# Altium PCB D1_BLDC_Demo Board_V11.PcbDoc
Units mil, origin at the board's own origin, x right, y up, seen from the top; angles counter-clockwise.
Board outline 2680 x 1610 mil, 2 copper layers (TopLayer, BottomLayer); 61 components, 42 nets, 192 pads, 108 vias.
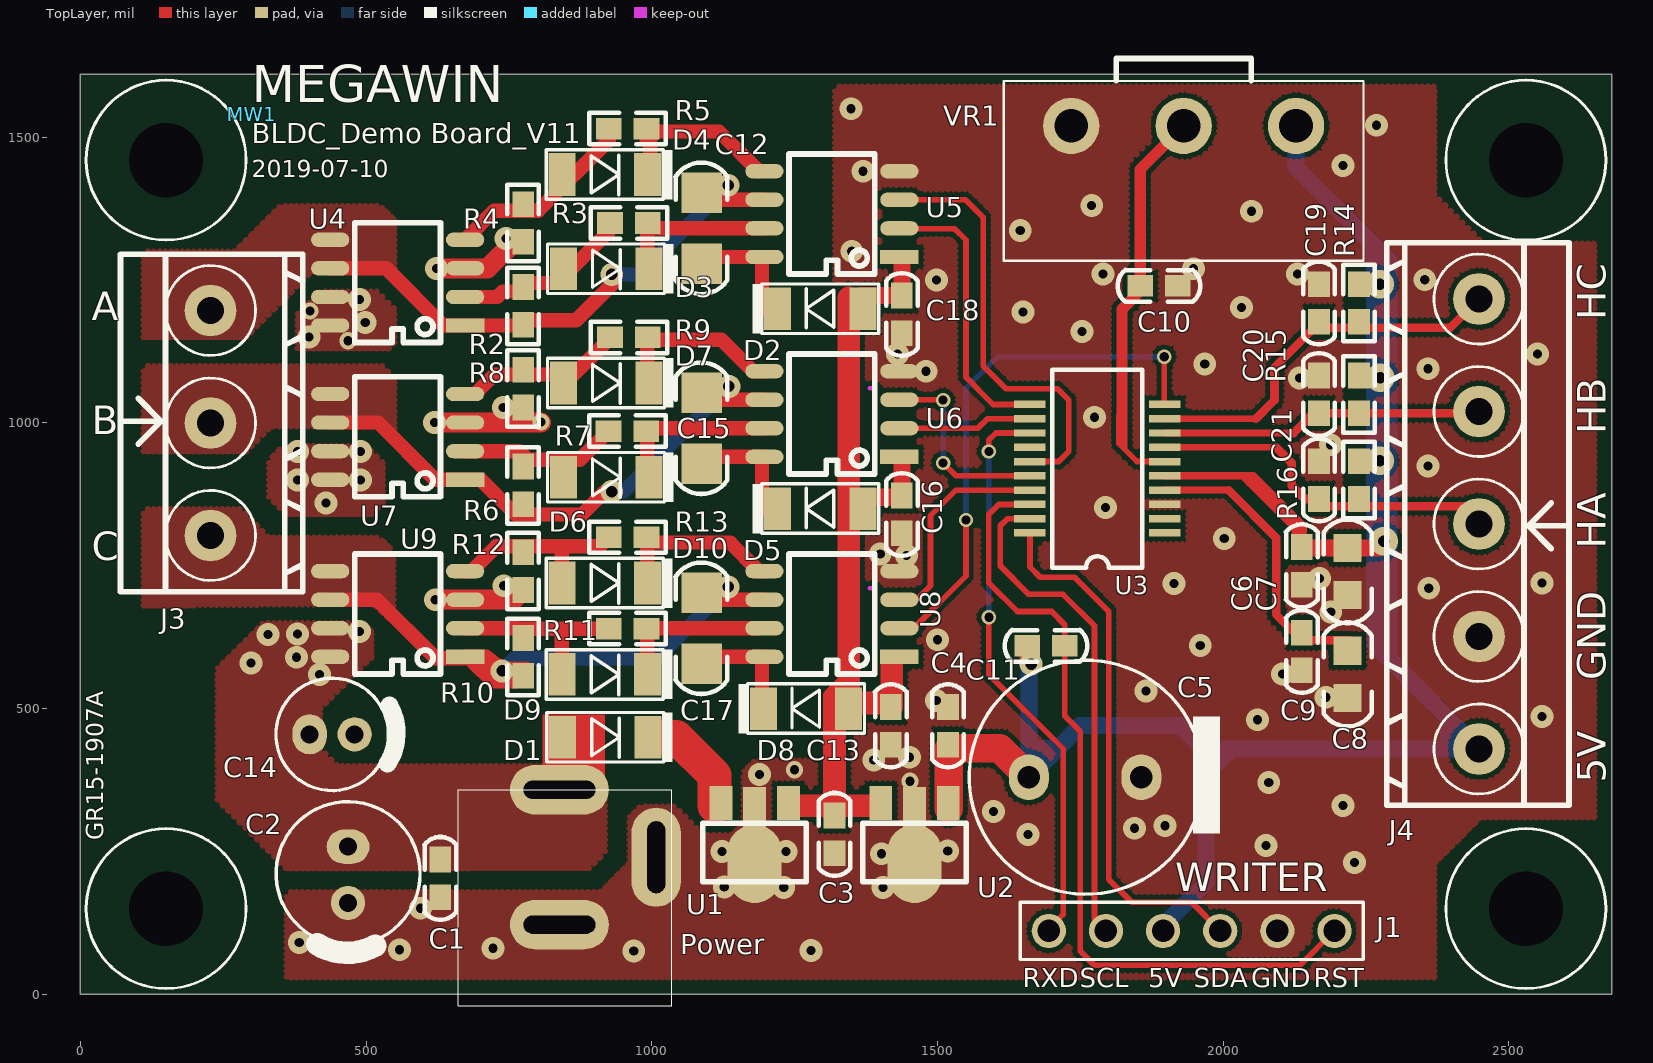
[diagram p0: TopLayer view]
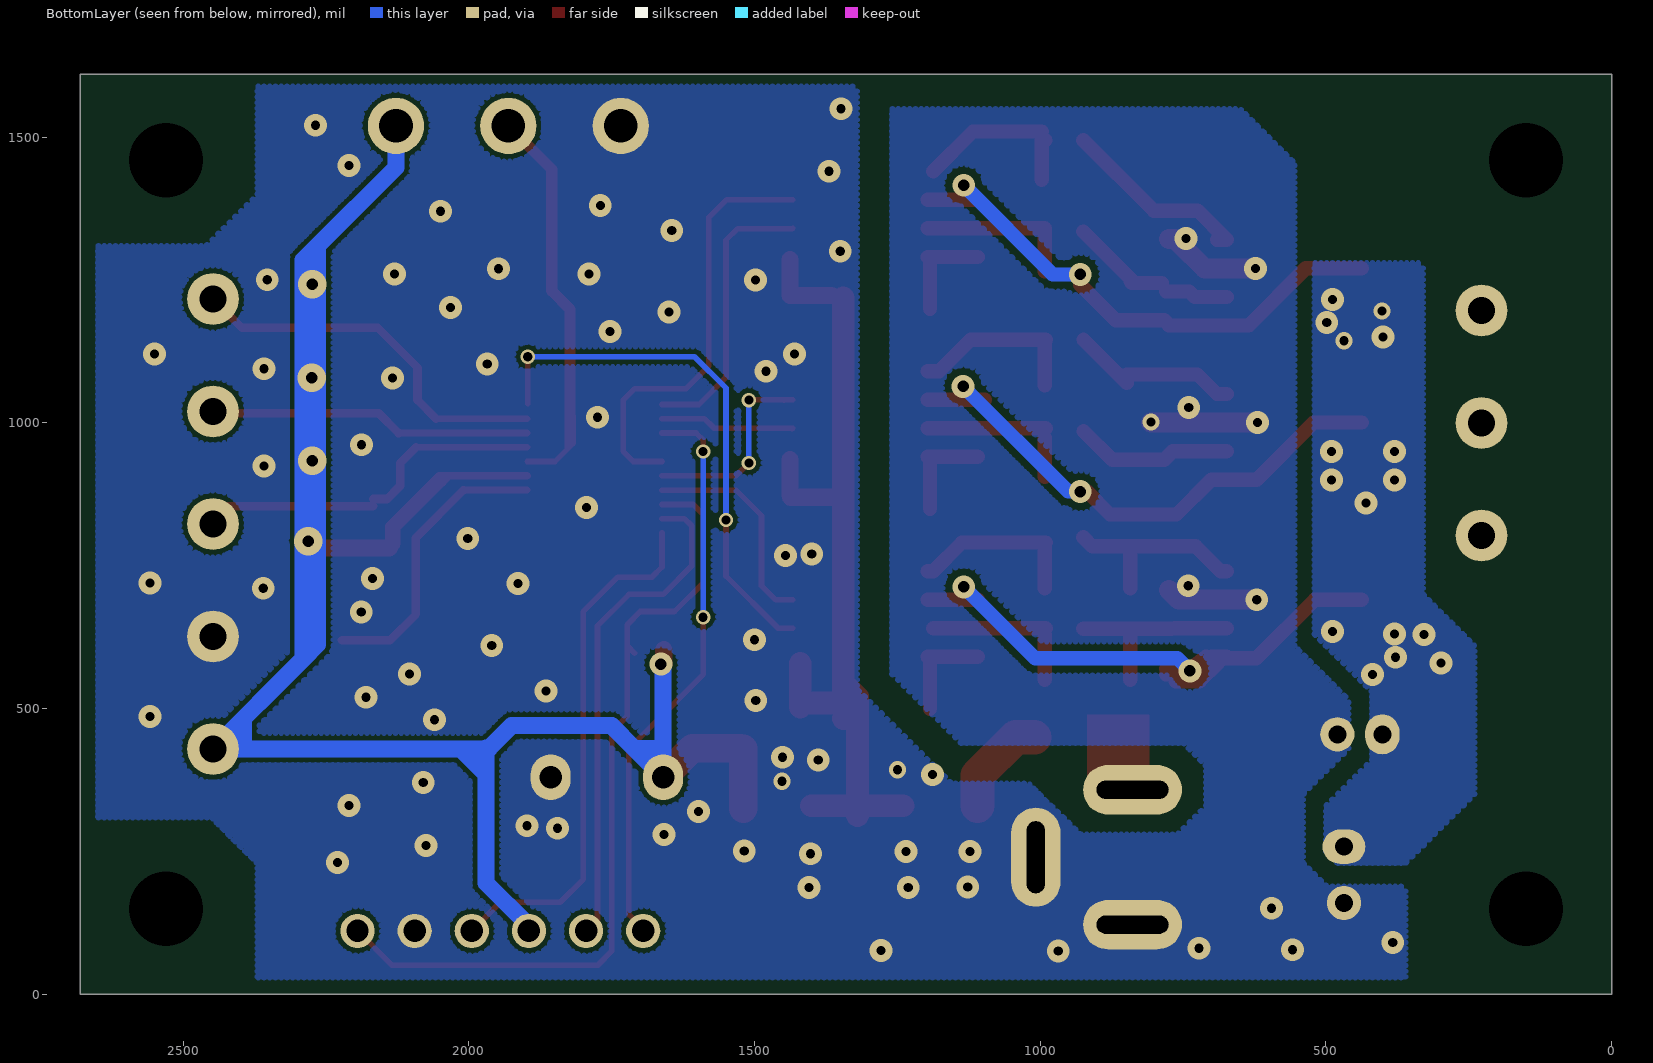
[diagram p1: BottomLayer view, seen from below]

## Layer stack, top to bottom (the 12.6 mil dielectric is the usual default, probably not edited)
TopLayer: signal copper 1.4
Dielectric: dielectric 12.6, FR-4, Dk 4.8
BottomLayer: signal copper 1.4

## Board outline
0,0 0,1610 2680,1610 2680,0

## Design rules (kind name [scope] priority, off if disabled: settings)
Clearance 12 [All] p1 off: gap=12
Clearance 10 [All] p2 off: gap=10
Clearance 8 [All] p3: gap=8
FabricationTestPointUsage TestPointUsage [All] p1: valid=0 allowmultiple=FALSE
FabricationTestpoint Testpoint [All] p1: side=3 testpointundercomponent=TRUE minsize=40 maxsize=100 preferedsize=60 minholesize=20 maxholesize=40 preferedholesize=32 testpointgrid=1 allowsidetop=TRUE allowsidebottom=TRUE usegrid=TRUE gridtolerance=0.01
HoleSize [All] p1: absolutevalues=TRUE maxlimit=500 minlimit=1 maxpercent=80.000 minpercent=20.000
PolygonConnect VIA [isvia] p1: connectstyle=Direct reliefconductorwidth=10 reliefentries=4 polygonreliefangle="90 Angle"
PolygonConnect PolygonConnect_1 [All] p2: connectstyle=Direct reliefconductorwidth=10 reliefentries=4 polygonreliefangle="90 Angle"
RoutingPriority [All] p1: routingpriority=4
RoutingVias [All] p1: holewidth=16 width=25 viastyle="Through Hole" minholewidth=16 minwidth=24 maxholewidth=28 maxwidth=50
SilkscreenOverComponentPads [All] p1: minsilkscreentomaskgap=10
SolderMaskExpansion [All] p1: expansion=4
Width [All] p1: maxlimit=100 minlimit=8 preferedwidth=10
23 further rules are at their usual default settings.

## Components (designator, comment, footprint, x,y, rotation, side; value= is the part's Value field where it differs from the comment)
C1 "0.1uF" 0603C 630,203 r90 top
C2 "35uF/35V" CEC060p025 468.46,258.43 r270 top
C3 "0.1uF" 0603C 1320,280 r90 top
C4 "0.1uF" 0603C 1518.46,470 r270 top
C5 "220uF_35V" CEC100p050 1758.42,380 r0 top
C6 "10uF" 0805C 2217.8,740 r270 top
C7 "0.1uF" 0603C 2137.8,750 r90 top
C8 "4.7uF" 0805C 2217.8,560 r270 top
C9 "0.1uF" 0603C 2137.8,600 r90 top
C10 "0.1uF" 0603C 1887.8,1240 r180 top
C11 "1uF" 0603C 1690,610 r180 top
C12 "10uF/1206" 1206C 1087.17,1340.67 r90 top
C13 "0.1uF" 0603C 1418.46,470 r90 top
C14 "10uF/50V" CEC5X11P2 440.63,455 r0 top
C15 "10uF/1206" 1206C 1087.17,990.67 r90 top
C16 "0.1uF" 0603C 1437.8,840 r90 top
C17 "10uF/1206" 1206C 1087.17,640.67 r90 top
C18 "0.1uF" 0603C 1437.8,1190 r90 top
C19 "0.1uF" 0603C 2167.8,1210 r270 top
C20 "0.1uF" 0603C 2167.8,1050 r270 top
C21 "0.1uF" 0603C 2167.8,900 r270 top
D1 "1N4148" D4148_SMD 918.46,450 r0 top
D2 "1N4148" D4148_SMD 1295,1200 r180 top
D3 "1N4148" D4148_SMD 920,1270 r0 top
D4 "1N4148" D4148_SMD 917.8,1435 r0 top
D5 "1N4148" D4148_SMD 1295,850 r180 top
D6 "1N4148" D4148_SMD 920,905 r0 top
D7 "1N4148" D4148_SMD 920,1070 r0 top
D8 "1N4148" D4148_SMD 1270,500 r180 top
D9 "1N4148" D4148_SMD 917.8,560 r0 top
D10 "1N4148" D4148_SMD 917.8,720 r0 top
J1 "CON6" PS6P254 1695,111 r0 top
J3 "Debug" PIN3_500_DT 227.8,1196.85 r270 top
J4 "CON5" PIN5_500_DT 2447.8,429.45 r90 top
MW1 "MEGAWIN" MEGAWIN_T 300,1540 r0 top
Power "DC JACK" JACK_DC 838.5,121.89 r90 top (schematic designator "Power 1")
R2 "30K" 0603R 775,1205 r270 top
R3 "33" 0603R 960,1350 r0 top
R4 "30K" 0603R 775,1350 r270 top
R5 "33" 0603R 957.8,1515 r0 top
R6 "30K" 0603R 775,890.67 r270 top
R7 "33" 0603R 957.17,985.67 r0 top
R8 "30K" 0603R 775,1060 r270 top
R9 "33" 0603R 960,1150 r0 top
R10 "30K" 0603R 775,590.67 r270 top
R11 "33" 0603R 957.8,640 r0 top
R12 "30K" 0603R 775,740.67 r270 top
R13 "33" 0603R 957.8,800 r0 top
R14 "1K" 0603R 2237.8,1210 r90 top
R15 "1K" 0603R 2237.8,1050 r90 top
R16 "1K" 0603R 2237.8,900 r90 top
U1 "UA78L15ACPK" SOT89 1180,335 r180 top
U2 "AIC1734A_50PXT / SOT89-3" SOT89 1460,335 r180 top
U3 "MG82F6D17_SSOP-20(150mil)" SSOP20_150P0635 1780,920 r90 top (schematic designator U6)
U4 "Si4946BEY" SO8_150P127 673.39,1170.67 r180 top
U5 "IR2101S" SO8_150P127 1433.39,1290.67 r180 top
U6 "IR2101S" SO8_150P127 1433.39,940.67 r180 top
U7 "Si4946BEY" SO8_150P127 673.39,900.67 r180 top
U8 "IR2101S" SO8_150P127 1433.39,590.67 r180 top
U9 "Si4946BEY" SO8_150P127 673.39,590.67 r180 top
VR1 "VR3-1" VR9_90 1930.94,1520 r270 top

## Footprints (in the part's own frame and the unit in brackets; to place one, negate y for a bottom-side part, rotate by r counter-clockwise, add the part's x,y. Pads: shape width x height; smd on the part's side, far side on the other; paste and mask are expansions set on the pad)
0603C [mil]
  rect 45x38 smd: 1(33,0) 2(-33,0)
  silkscreen extent -72,-28 72,28
0603R [mil]
  rect 45x38 smd: 1(33,0) 2(-33,0)
  silkscreen extent -67,-28 67,28
0805C [mm]
  rect 1.25x1.25 smd: 1(-1.05,0) 2(1.05,0)
  silkscreen extent -2.31,-1.07 2.31,1.07
1206C [mm]
  rect 1.8x1.8 smd: 1(-1.576,0) 2(1.576,0)
  silkscreen extent -2.92,-1.15 2.92,1.16
CEC5X11P2 [mil]
  oval 60x70 hole 31.5: 1(-39.37,0)
  round 60 hole 31.5: 2(39.37,0)
  silkscreen extent -98,-98 113,98
CEC060p025 [mil]
  oval 60x75 hole 31.5: 1(0,0)
  round 60 hole 31.5: 2(98.43,0)
  silkscreen extent -79,-126 186,126
CEC100p050 [mil]
  oval 70x80 hole 39.37: 1(-98.42,0) 2(98.42,0)
  silkscreen extent -203,-205 236,205
D4148_SMD [mm]
  rect 1.2x1.9 smd: 1(-1.9,0) 2(1.9,0)
  silkscreen extent -2.6,-1.1 3,1.1
JACK_DC [mm]
  oval 2.2x4.4 hole 0.8 slot 3.2 at 90 deg: 1(0,0) 3(6,0)
  oval 4.4x2.2 hole 0.8 slot 3.2 at 0 deg: 2(3,-4.3)
  silkscreen extent -3.6,-5 6,4.5
MEGAWIN_T [mil]
PIN3_500_DT [mm]
  round 2.3 hole 1.2: 1(0,0) 2(5,0) 3(10,0)
  silkscreen extent -2.5,-4 12.5,4.1
PIN5_500_DT [mm]
  round 2.3 hole 1.2: 1(0,0) 2(5,0) 3(10,0) 4(15,0) 5(20,0)
  silkscreen extent -2.5,-4 22.5,4.1
PS6P254 [mil]
  round 60 hole 39.37: 1(0,0) 2(100,0) 3(200,0) 4(300,0) 5(400,0) 6(500,0)
  silkscreen extent -50,-50 550,50
SO8_150P127 [mil]
  rect 67x25 smd: 1(0,0)
  oval 67x25 smd: 2(0,-50) 3(0,-100) 4(0,-150) 5(236.22,-150) 6(236.22,-100) 7(236.22,-50) 8(236.22,0)
  silkscreen extent 43,-180 193,30
SOT89 [mm]
  rect 1.016x1.5 smd: 1(-1.5,0) 3(1.5,0)
  oval 2.4x3.5 smd: 2(0,2.7)
  rect 1.016x2.6 smd: 2(0,0.6)
  silkscreen extent -2.3,0.9 2.3,3.5
SSOP20_150P0635 [mil]
  rect 13x55.12 smd: 1(-112.5,-118.11) 2(-87.5,-118.11) 3(-62.5,-118.11) 4(-37.5,-118.11) 5(-12.5,-118.11) 7(37.5,-118.11) 8(62.5,-118.11) 9(87.5,-118.11) 10(112.5,-118.11) 11(112.5,118.11) 12(87.5,118.11) 13(62.5,118.11) 14(37.5,118.11) 15(12.5,118.11) 16(-12.5,118.11) 17(-37.5,118.11) 18(-62.5,118.11) 19(-87.5,118.11) 20(-112.5,118.11)
  rect 13x55.12 smd mask+4: 6(12.5,-118.11)
  silkscreen extent -173,-79 173,79
VR9_90 [mm]
  round 2.5 hole 1.5: 1(0,5) 2(0,0) 3(0,-5)
  silkscreen extent -3,-8 6,8

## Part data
C1 C3 C4 C8 C9: library part "CAP NP_Dup1"
C2 C5: library part CAP_Dup1
C6 C7 C10 C11 C13 C16 C18 C19 C20 C21: library part "CAP NP"
C12 C14 C15 C17: library part CAP
D1 D2 D5 D8: library part ES1A/SM
J3: library part CON3
R2 R4 R6 R8 R10 R12: library part R
R3 R5 R7 R9 R11 R13 R14 R15 R16: library part RESISTOR
U2: library part AIC1734A_50PXT
U3: library part MG82G6D17_SSOP-20

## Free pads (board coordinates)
  round 100 hole 130 unplated: 1(150,150) 1(150,1460) 1(2530,150) 1(2530,1460)

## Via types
v1: diameter 40, hole 16, TopLayer to BottomLayer, tented both sides, 86 vias
v2: diameter 40, hole 20, TopLayer to BottomLayer, tented both sides, 7 vias
v3: diameter 25, hole 16, TopLayer to BottomLayer, 6 vias
v4: diameter 30, hole 16, TopLayer to BottomLayer, tented both sides, 5 vias
v5: diameter 50, hole 20, TopLayer to BottomLayer, tented both sides, 4 vias

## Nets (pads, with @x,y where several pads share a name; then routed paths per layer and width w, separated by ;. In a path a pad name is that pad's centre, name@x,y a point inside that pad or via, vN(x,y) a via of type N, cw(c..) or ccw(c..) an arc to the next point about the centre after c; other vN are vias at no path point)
15V: C3.1 C13.1 C16.1 C18.1 D2.1 D5.1 D8.1 U1.1 U2.3 U5.1 U6.1 U8.1 | length 1578.4
  TopLayer w25: 1312.37,522.37 1344.8,554.8
  TopLayer w30: D5.1@1364.8,870 C16.1@1437,870 ; D2.1@1365.6,1223 C18.1 U5.1@1437.8,1286.26 ; C16.1 U6.1@1437.8,936.26
  TopLayer w40: U1.1@1240,330 C3.1@1320,330 ; C3.1 C3.1@1320,330 ; 1320,520 1320,483 ; D8.1@1344.8,483 1320,483 ; D8.1 D8.1@1344.8,510 ; 1344.8,1219.2 1344.8,554.8 D8.1@1344.8,510 ; U2.3@1400.94,330 C3.1@1320,330 ; C13.1@1418.46,510 D8.1@1344.8,510 ; C13.1@1420,503 U8.1@1420,579 ; C3.1@1320,330 1320,483
"A DET": C21.1 J4.3 R16.2 U3.7 | length 635.8
  TopLayer w12: U3.7 2092.5,957.5
  TopLayer w15: 2092.5,957.5 2120,930 2120,890 2143,867 C21.1 ; C21.1@2167.8,854.21 2266,854.21 ; 2282.01,854.21 2266,854.21 ; J4.3@2457,854.21 2266,854.21
AB: U3.15 U5.3 | length 759.5
  TopLayer w10: U5.3 1549.33,1390.67 1580,1360 1580,1100 1620,1060 1710,1060 1730,1040 1730,950 1712.5,932.5 U3.15
AT: U3.11 U5.2 | length 496.7
  TopLayer w10: U5.2 1434.06,1340 1530,1340 1550,1320 1550,1080 1597.5,1032.5 U3.11
"B DET": C20.1 J4.4 R15.2 U3.8 | length 561
  TopLayer w12: U3.8 2123.3,982.5
  TopLayer w15: 2123.3,982.5 2157.8,1017 C20.1 R15.2 J4.4@2444.8,1017
BB: U3.16 U6.3 | length 362.5
  TopLayer w10: U6.3@1448.46,1040 1447.8,1040.67 U6.3 v3@1509.33,1040.67 ; v3(1510,930) 1532.5,907.5 U3.16
  BottomLayer w10: v3(1510,930) v3(1510,1040)
BT: U3.12 U6.2 | length 236.4
  TopLayer w10: U6.2@1434.06,990 U6.2 1570.67,990.67 1587.5,1007.5 U3.12
"C DET": C19.1 J4.5 R14.2 U3.9 | length 669.8
  TopLayer w12: U3.9 2057.5,1007.5
  TopLayer w15: 2057.5,1007.5 2090,1040 2090,1097 2160,1167 2167.8,1167 2397.94,1167 J4.5
CB: U3.17 U8.3 | length 379.9
  TopLayer w10: U8.3 1463.46,690.67 1487.8,715 1487.8,837.8 1532.5,882.5 U3.17
CT: U3.10 U8.2 | length 935.5
  TopLayer w10: U8.2 1458.46,640.67 1550,732.2 v3(1550,830) ; U3.10@1897,1033.61 v3(1897,1116)
  BottomLayer w10: v3(1550,830) 1550,1061 1605,1116 v3(1897,1116)
DC+: C1.1 C2.1 C14.1 D1.1 Power.3 U4.7 U4.8 U7.7 U7.8 U9.7 U9.8
  other v1: 418.46,560 298.46,580 378.46,590 328.46,630 380,630.63 488.46,635 430,860 380,900 490,900 380,950 490,950 400,1150.63 498.46,1176 488.46,1216
  other v4: 468.46,1144 402,1196
GND: C1.2 C2.2 C3.2 C4.2 C5.2 C6.2 C7.2 C8.2 C9.2 C10.2 C13.2 C14.2 C16.2 C18.2 C19.2 C20.2 C21.2 J1.5 J4.2 Power.1 Power.2 R4.1 R8.1 R12.1 U1.2 U2.2 U3.3 U4.3 U5.4 U6.4 U7.3 U8.4 U9.3 VR1.3 | length 522.8
  TopLayer w35: v1@618.46,1000.67 v1(620,1000.63) U7.3 740,1000.67 775,1000.67 v4@806,1000.67 ; v1@620,690.67 v1(621,690.63) U9.3 741,690.67 758,690.67 761.67,694.33 R12.1 ; v1(623,1270.67) U4.3 712.67,1270.67 755,1313 764,1322 R4.1@775,1322
  other v1: 968.46,76 1278.46,77 558.46,78 722,80.63 383,90.63 595,150.63 1231,187 1405,187 1127,188 2230,230.63 1402,246 1123,250 1235,250 1518,251 2075,260.63 1658.46,280 1845,290.63 1898.46,295 1598.46,320 2210,330.63 2080,370.63 1188.46,385 1388.46,410 1451,415 2060,480.63 2558.46,486 1498,514 2180,520 1865,530.63 2104,560.63 1960,610.63 1500,620.63 2188.46,669 2360,710.63 741,715 1914,719 2558.46,720 2168.46,728 1446,768 1400,770.63 2002,798 1794,852 2358.46,925 2188,962 1775,1010 740,1027 2134,1079 1480,1090.63 2358.46,1095 1968,1103 1430,1120.63 2550,1120.63 1753,1160 1650,1194 2032,1202 1498.46,1250 2353,1250.63 1790,1260.63 2130,1260.63 1948.46,1270 1350,1300.63 745,1323 1645,1337 2050,1370.63 1770,1380.63 1370,1440.63 2210,1450.63 2268.46,1521 1348.46,1550
  other v4: 1452,373 1250,393 806,1002
NetC12_1: C12.1 D2.2 U5.8 | length 174.4
  TopLayer w25: C12.1@1109.22,1290.67 U5.8 ; 1192.99,1200 U5.8@1192.99,1286.5
NetC15_1: C15.1 D5.2 U6.8 | length 174.4
  TopLayer w25: C15.1@1109.22,940.67 U6.8 ; 1192.99,850 U6.8@1192.99,936.5
NetC17_1: C17.1 D8.2 U8.8 | length 174.4
  TopLayer w25: C17.1@1109.22,590.67 U8.8 ; D8.2@1192.99,500 U8.8@1192.99,586.5
NetD1_2: D1.2 U1.3 | length 180.7
  TopLayer w60: D1.2@1010,450 1042.99,450 1110,382.99 1110,335 U1.3@1110,330
NetD3_1: D3.1 R2.2 R3.2 U4.2 | length 293.1
  TopLayer w25: U4.2 729.67,1220.67 739,1230 R2.2@780,1230 ; R2.2@787.2,1245 D3.1@834.8,1245 ; D3.1@840,1245 D3.1@834.8,1245 ; D3.1@842.99,1250.67 D3.1@840.46,1250.67 ; R3.2@924.8,1335 D3.1@840.46,1250.67 ; D3.1@834.8,1245 D3.1@840.46,1250.67
NetD3_2: D3.2 R3.1 U5.7 | length 274.5
  TopLayer w25: D3.2@991.97,1265.67 R3.1@991.97,1335 ; R3.1@991.97,1340.67 U5.7
NetD4_1: D4.1 R4.2 R5.2 U4.4 | length 340.9
  TopLayer w25: U4.4@690.67,1320.67 U4.4 724.41,1371.69 801.49,1371.69 924.8,1495
NetD4_2: D4.2 R5.1 U5.5 | length 298.1
  TopLayer w25: 990.8,1495 997.17,1495 ; D4.2@997.17,1425.67 997.17,1495 ; R5.1@997.17,1498.67 997.17,1495 ; R5.1@997.17,1510 1117.83,1510 U5.5@1187.17,1440.67
NetD6_1: D6.1 R6.2 R7.2 U7.2 | length 277.7
  TopLayer w25: U7.2 768,950.67 783,935.67 874.17,935.67 R7.2
NetD6_2: D6.2 R7.1 U6.7 | length 275.2
  TopLayer w25: R7.1@990.17,990.67 U6.7 ; D6.2@991.97,905.67 R7.1@991.97,973.87
NetD7_1: D7.1 R8.2 R9.2 U7.4 | length 296.3
  TopLayer w25: U7.4 690.67,1050.67 725,1085 D7.1@848.5,1085 ; D7.1@848.5,1070 R9.2@924.17,1145.67
NetD7_2: D7.2 R9.1 U6.5 | length 308
  TopLayer w25: R9.1@990.17,1145.67 1122.17,1145.67 1177.17,1090.67 U6.5 ; D7.2@991.97,1065.67 R9.1@991.97,1143.87
NetD9_1: D9.1 R10.2 R11.2 U9.2 | length 334.1
  TopLayer w25: U9.2 R10.2@764.17,640.67 ; R10.2@770.83,640 775,640 842.36,640 ; D9.1@842.36,550.67 842.36,560 842.36,640 ; R11.2 842.36,640
NetD9_2: D9.2 R11.1 U8.7 | length 275.2
  TopLayer w25: R11.1@990.17,640.67 990.8,640.67 U8.7@1187.17,640.67 ; D9.2@991.97,550.67 991.97,560 R11.1@991.97,628.87
NetD10_1: D10.1 R12.2 R13.2 U9.4 | length 346
  TopLayer w25: U9.4 684.46,740.67 727.8,784 908.8,784 R13.2 ; D10.1@842.36,710.67 842.36,780.67
NetD10_2: D10.2 R13.1 U8.5 | length 305.9
  TopLayer w25: R13.1@990.17,790.67 1137.17,790.67 1187.17,740.67 U8.5 ; D10.2@991.97,710.67 R13.1@991.97,788.87
NetJ2_1: 
NetJ2_2: 
NetJ2_3: 
OCD_SCL: J1.2 U3.19 | length 877.8
  TopLayer w10: U3.19 1622.5,832.5 1610,820 1610,750 1660,700 1720,700 1775,645 1775,131 J1.2
OCD_SDA: J1.4 U3.20 | length 931.1
  TopLayer w10: U3.20 1661.89,748.11 1680,730 1740,730 1800,670 1800,201 1840,161 1945,161 J1.4
RST: C11.2 J1.6 U3.18 | length 1443.6
  TopLayer w10: U3.18 1607.5,857.5 1590,840 1590,720 1640,670 1700,670 1723,647 1723,487 1750,460 1750,75.63 1774.63,51 2134.37,51 J1.6@2195,111.63 ; C11.2@1710,597 C11.2
RXD0: J1.1 U3.13 | length 1000.9
  TopLayer w10: v3(1590,660) 1590,560 1720,430 1720,139.63 J1.1@1692,111.63 ; v3(1590,950) 1590,970 1602.5,982.5 U3.13
  BottomLayer w10: v3(1590,660) v3(1590,950)
RXD1: 
U: C12.2 J3.1 R2.1 U4.1 U4.5 U4.6 U5.6 | length 966.4
  TopLayer w25: U4.6 535.13,1270.67 635.13,1170.67 U4.1 ; U4.1@702,1170.67 U4.1 ; R2.1@775,1170.67 U4.1 ; R2.1 783,1180 868,1180 930,1242 v2(930,1260) ; C12.2@1109.22,1390.67 U5.6
  BottomLayer w25: v2(930,1260) 978,1260 v2(1134,1416)
V: C15.2 J3.2 R6.1 U6.6 U7.1 U7.5 U7.6 | length 945
  TopLayer w25: U7.6 521.13,1000.67 621.13,900.67 U7.1 700.8,900.67 761.46,840 877.8,840 v2@917.8,880 ; C15.2@1097.17,1040.67 U6.6
  BottomLayer w25: v2(930,880) 951,880 v2(1135,1064)
VDD5V: C4.1 C5.1 C6.1 C7.1 C11.1 J1.3 J4.1 R14.1 R15.1 R16.1 U2.1 U3.5 VR1.1 | length 4404.5
  TopLayer w13: U3.5 2052.5,907.5 2140,820 C7.1@2140,790
  TopLayer w15: 2036.38,906.62 2058.4,884.6 ; C7.1@2132,788.8 C7.1 C7.1@2139.46,781.34
  TopLayer w25: 2050,900 2132,818 C7.1@2132,788.8
  TopLayer w30: v2@1659,578 C11.1@1659,603 ; C7.1@2139.46,781.34 C6.1 v5@2272.04,781.34
  TopLayer w50: U2.1@1520,325 1520,335 C4.1@1520,430 ; C4.1@1525,430.63 1609.37,430.63 C5.1
  BottomLayer w30: v2@1660,578 C5.1 1710.02,430.02 ; 1661.55,429.91 1710.02,430.02 ; J1.3@1895,120 1970,195 1970,429.45 ; 1965,429.45 1970,429.45 ; 1965,430.63 1924.92,470.52 1750.09,470.09 1710.02,430.02 ; 1970,430.63 1970,429.45 ; 1972.86,387.73 2012.75,427.82 ; VR1.1 2127.8,1447.2 2265,1310 ; 2394.92,478.68 2395.04,430.21 ; 1970,429.45 J4.1 2290,587.24 ; 2265,1310 2265,1243 2265,1079 2265,934 2265,793 2265,612.24 2290,587.24 ; 2265,1310 2290,1285 2290,1243 2290,1079 2290,934 2290,793 2290,587.24
  other v2: 1664,578
  other v5: 2281,793 2274,934 2275,1079 2274,1243
VR0: C8.1 C9.1 U3.4 | length 512
  TopLayer w12: U3.4 2009.5,882.5
  TopLayer w15: 2009.5,882.5 2092.8,799.2 2092.8,665 2137.8,620 C8.1@2222.8,620
VSP: C10.1 U3.6 VR1.2 | length 709.9
  TopLayer w10: 1818,1013 1818,964 1849.5,932.5 U3.6
  TopLayer w19.68: 1823,997 1823,1199 1854.8,1230.8 C10.1 1854.8,1443.85 VR1.2
W: C17.2 J3.3 R10.1 U8.6 U9.1 U9.5 U9.6 | length 1133.1
  TopLayer w25: U9.6 519.33,690.67 622,588 673.39,588 U9.1 699.33,590.67 U9.1@702,588 ; U9.1@688.64,580.36 720.5,548.5 721,548 738,548 748,548 ; U9.1@699.33,588 U9.1@702,588 ; 710,591 v2@735.64,571.36 ; v2@730.39,565.61 734,562 v2@736,560 ; R10.1@763,548 748,548 ; R10.1@780,560 775,560 738,560 v2@736,560 ; R10.1@780,570 775,570 738,570 720,570 U9.1@702,588 ; C17.2@1109.22,690.67 1134,690.67 U8.6 ; v2@736,560 748,548
  BottomLayer w25: v2(738,566) 760,588 1009,588 v2(1134,713)
pads on no net: U3.1 U3.2 U3.14

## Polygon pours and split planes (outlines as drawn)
DC+ on TopLayer "Bottom Layer-No Net 1" (hatched 90Degree grid 10 track 10, remove dead copper, pour order 1004): 240,570 240,340 360.27,219.73 479.04,220.19 890.63,220.63 918.46,248.46 918.46,370 891.44,400.19 450,400 420,430 420,500 510,590 510,635 495,650 320,650
DC+ on TopLayer "Bottom Layer-No Net 1" (hatched 90Degree grid 10 track 10, remove dead copper, pour order 1006): 380,1130 540,1130 550,1140 550,1200 520,1230 420,1230 380,1190
U on TopLayer "Bottom Layer-No Net 1" (hatched 90Degree grid 10 track 10, remove dead copper, pour order 1005): 110,1300 270,1300 350,1380 525,1380 550,1355 550,1255.8 540.8,1265 405,1265 290,1150 110,1150
DC+ on TopLayer "Bottom Layer-No Net 1" (hatched 90Degree grid 10 track 10, remove dead copper, pour order 1003): 355,960 500,960 530,930 530,860 510,840 360,840 330,870 330,935
V on TopLayer "Bottom Layer-No Net 1" (hatched 90Degree grid 10 track 10, remove dead copper, pour order 1002): 110,1100 529,1100 550,1079 550,965.35 522.2,993.15 333.15,993.15 290,950 110,950
W on TopLayer "Bottom Layer-No Net 1" (hatched 90Degree grid 10 track 10, remove dead copper, pour order 1001): 110,850 280,850 330,800 523,800 548.46,774.54 548.46,649.37 512.2,683.15 110,680
GND on TopLayer "Bottom Layer-No Net 1" (hatched 90Degree grid 10 track 10, remove dead copper, pour order 1000): 360.63,179.37 360.63,29.37 2370.63,29.37 2370.63,229.37 2450.63,309.37 2650.63,309.37 2650.63,1314.65 2455.35,1314.65 2370.63,1399.37 2370.63,1589.37 1320.63,1589.37 1320.63,440 1290,409.37 1180.63,409.37 1160.63,389.37 1160.63,298.94 1140.63,279.37 1090.08,279.37 1040.63,329.37 980.63,329.37 960.63,309.37 960.63,229.37 910.63,179.37
GND on BottomLayer "Bottom Layer-No Net 1" (hatched 90Degree grid 10 track 10, remove dead copper, pour order 1008): 750,440 1139,440 1260,561 1260,1550 650,1550 555,1455 555,610 460,515 460,430 540,350 540,229.75 458.83,150.61 460,120.58 710,120.63 1058.46,120 1058.46,330 980,330 930,280 760,280 710,330 710,400
DC+ on BottomLayer "Bottom Layer-No Net 1" (hatched 90Degree grid 10 track 10, remove dead copper, pour order 1009): 330,700 330,1280 520,1280 520,630 420,530 420,410 500,330 500,250 480,230 360,230 240,350 240,610
GND on BottomLayer "Bottom Layer-No Net 1" (hatched 90Degree grid 10 track 10, pour order 1007): 360.63,189.37 360.63,29.37 2370.63,29.37 2370.63,229.37 2450.63,309.37 2649.09,309.37 2649.09,1310 2460,1310 2370.63,1399.37 2370.63,1589.37 1320.63,1589.37 1320.63,534.37 1155.63,369.37 1020.63,369.37 960.63,309.37 960.63,229.37 920.63,189.37

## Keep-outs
TopLayer:
  lines w8: 1381.8,710.63 1390.66,710.63 ; 1381.8,1060.63 1390.66,1060.63

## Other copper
TopLayer:
  rectangle net VSP: 1818,957.22 1825.78,997
  rectangle net VSP: 1825.78,956.22 1833,1007
  rectangle net DC+: 808.46,350 918.46,490

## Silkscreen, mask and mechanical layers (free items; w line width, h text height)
TopOverlay:
  circle w5: c150,1460 r140
  circle w5: c2530,1460 r140
  circle w5: c2530,150 r140
  circle w5: c150,150 r140
  text "BLDC_Demo Board_V11" at 300,1490 h35
  text "2019-07-10" at 300,1430 h30
  text "A" at 20,1180 h50
  text "HC" at 2670,1180 h50 r90
  text "B" at 20,980 h50
  text "HB" at 2670,980 h50 r90
  text "HA" at 2670,780 h50 r90
  text "C" at 20,760 h50
  text "GND" at 2670,550 h50 r90
  text "5V" at 2670,370 h50 r90
  text "GR15-1907A" at 40,270 h30 r90
  text "WRITER" at 1916.03,180.63 h50
  text "RXD" at 1649,12 h33
  text "SCL" at 1749,12 h33
  text "5V" at 1869,12 h33
  text "SDA" at 1949,12 h33
  text "GND" at 2049,12 h33
  text "RST" at 2159,12 h33
Mechanical1:
  the board outline again, w10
